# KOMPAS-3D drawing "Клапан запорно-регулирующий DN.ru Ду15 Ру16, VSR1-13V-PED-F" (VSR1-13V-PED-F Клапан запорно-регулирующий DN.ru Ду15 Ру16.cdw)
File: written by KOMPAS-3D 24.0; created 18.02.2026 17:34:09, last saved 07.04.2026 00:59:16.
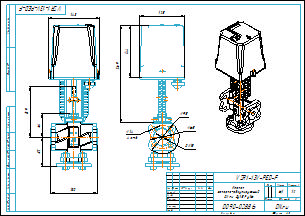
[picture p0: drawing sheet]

Document properties: Автор: R2D2; Форматы листов документа: A3; Полное имя файла: VSR1-13V-PED-F Клапан запорно-регулирующий DN.ru Ду15 Ру16.m3d; Масса: 6.1; Наименование: Клапан запорно-регулирующий DN.ru Ду15 Ру16; Количество листов документа: 1; Примечание: D090-02886

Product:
- Part/product: Клапан запорно-регулирующий DN.ru Ду15 Ру16  | designation VSR1-13V-PED-F
    Масса: 6.1
    Раздел спецификации: Прочие изделия
    Форматы листов документа: A3
    Примечание: D090-02886

Views: Вид 1, Спереди
Referenced files in E:\Работа\Зайцев\Солянка\VSR1-13V-PED-F Клапан запорно-регулирующий DN.ru\DN15\DN15 Kv0.16\: VSR1-13V-PED-F Клапан запорно-регулирующий DN.ru Ду15 Ру16.m3d
Referenced files in E:\Работа\Зайцев\Для компаса\: чертеж DN.ru А3.cdt
Referenced files in E:\Работа\Зайцев\Солянка\VSR1-13V-PED-F Клапан запорно-регулирующий DN.ru\DN15\DN15 Kv4\: VSR1-13V-PED-F Клапан запорно-регулирующий DN.ru Ду15 Ру16.m3d
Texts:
  Линейный размер
  VSR1-13V-PED-F
  чертеж DN.ru А3.cdt
  Клапан
  запорно-регулирующий
  DN.ru Ду15 Ру16
  Клапан запорно-регулирующий DN.ru Ду15 Ру16
  VSR1-13V-PED-F Клапан запорно-регулирующий DN.ru Ду15 Ру16
Dimensions and other numbers on the sheet: 0; 3; 2; 4; 130; 82; 143; 64; 139; 1:2; 1; 6,1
